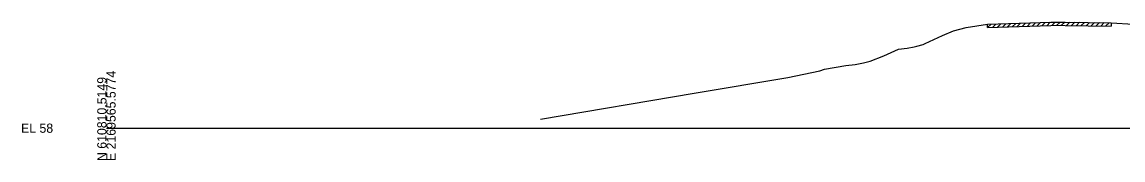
# Model space of a CAD drawing. Extents: x -26 to 6803, y -10 to 19606.
# Drawn here: x 1974.3 to 2309.3, y 7990.3 to 8032.4 of the extents above; entities that cross this region are included whole.
import ezdxf

# ---------------------------------------------------------------- set-up
doc = ezdxf.new("R2010")
doc.units = 0
for name, color, linetype in [('RD_GPK_XS_Cell', 7, 'Continuous'), ('RD_XS_ExGround', 7, 'Continuous'), ('RD_XS_ExPaveRet', 7, 'Continuous')]:
    doc.layers.add(name, color=color, linetype=linetype)

msp = doc.modelspace()

# ---------------------------------------------------------------- linework, layer by layer
at = {"layer": 'RD_GPK_XS_Cell'}
msp.add_line((2000, 8000), (2400, 8000), dxfattribs=at)
at = {"layer": 'RD_XS_ExGround'}
msp.add_lwpolyline([(2132.08, 8002.78), (2178.86, 8010.63), (2207.39, 8015.47), (2217.12, 8017.52), (2218.5, 8017.97), (2225.01, 8019.11), (2227.85, 8019.43), (2230.33, 8019.96), (2232.38, 8020.45), (2236.52, 8022.02), (2241.07, 8024.03), (2243.61, 8024.4), (2245.78, 8024.82), (2246.57, 8024.99), (2248.48, 8025.46), (2249.16, 8025.76), (2254.41, 8028.21), (2257.73, 8029.63), (2261.61, 8030.72), (2268.15, 8031.64), (2287.34, 8032.26), (2290.29, 8032.35), (2291.7, 8032.33), (2305.78, 8032.11), (2312.52, 8031.65)], dxfattribs=at)
at = {"layer": 'RD_XS_ExPaveRet'}
for p, q in [((2268.15, 8030.64), (2269.19, 8031.67)), ((2268.15, 8030.64), (2268.15, 8031.64)), ((2268.15, 8030.64), (2287.34, 8031.26)), ((2269.65, 8030.69), (2270.69, 8031.72)), ((2271.15, 8030.73), (2272.19, 8031.77)), ((2272.65, 8030.78), (2273.69, 8031.82)), ((2274.15, 8030.83), (2275.19, 8031.87)), ((2275.65, 8030.88), (2276.69, 8031.92)), ((2277.15, 8030.93), (2278.19, 8031.96)), ((2278.65, 8030.98), (2279.69, 8032.01)), ((2280.15, 8031.03), (2281.19, 8032.06)), ((2281.65, 8031.08), (2282.69, 8032.11)), ((2283.15, 8031.13), (2284.19, 8032.16)), ((2284.65, 8031.18), (2285.69, 8032.21)), ((2286.15, 8031.22), (2287.19, 8032.26)), ((2287.34, 8031.26), (2290.29, 8031.35)), ((2287.65, 8031.27), (2288.68, 8032.3)), ((2289.15, 8031.32), (2290.18, 8032.35)), ((2290.29, 8031.35), (2291.7, 8031.33)), ((2290.65, 8031.35), (2291.64, 8032.33)), ((2291.7, 8031.33), (2305.78, 8031.11)), ((2292.15, 8031.33), (2293.14, 8032.31)), ((2293.65, 8031.3), (2294.64, 8032.29)), ((2295.15, 8031.28), (2296.14, 8032.26)), ((2296.65, 8031.26), (2297.64, 8032.24)), ((2298.15, 8031.23), (2299.14, 8032.22)), ((2299.65, 8031.21), (2300.64, 8032.19)), ((2301.15, 8031.19), (2302.14, 8032.17)), ((2302.65, 8031.16), (2303.64, 8032.15)), ((2304.15, 8031.14), (2305.14, 8032.12)), ((2305.78, 8032.11), (2305.78, 8031.11)), ((2305.78, 8031.11), (2305.78, 8031.11))]:
    msp.add_line(p, q, dxfattribs=at)

# ---------------------------------------------------------------- texts
at = {"layer": 'RD_GPK_XS_Cell'}
for s, p in [('E 2169565.5774', (2002.8, 7990)), ('N 610810.5149', (2000, 7990))]:
    msp.add_text(s, height=2.8, rotation=90, dxfattribs=at).set_placement(p)
msp.add_text('EL 58', height=2.8, dxfattribs=at).set_placement((1974, 7998.6))

doc.saveas('drawing.dxf')
